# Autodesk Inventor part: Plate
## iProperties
Shininess: 64.0
Length Units: 11269
Angle Units: 11279
Time Units: 11290
Mass Units: 11283
Length Display Precision: 3
Angle Display Precision: 2
Compacted: True
Part Number: Plate
Document SubType Name: Modeling
Created: 2003-08
Designer: 40664
Manufacturer: Standard
Standards Organization: Custom
Density: 0.0
Volumn: 0.0
Area: 0.0
PropertySet Name: Model Information
Control State: 0
Master: False
Checked Out: False
Author: 40664
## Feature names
1. Extrusion1
2. Hole1
3. Hole2
4. Fillet1
